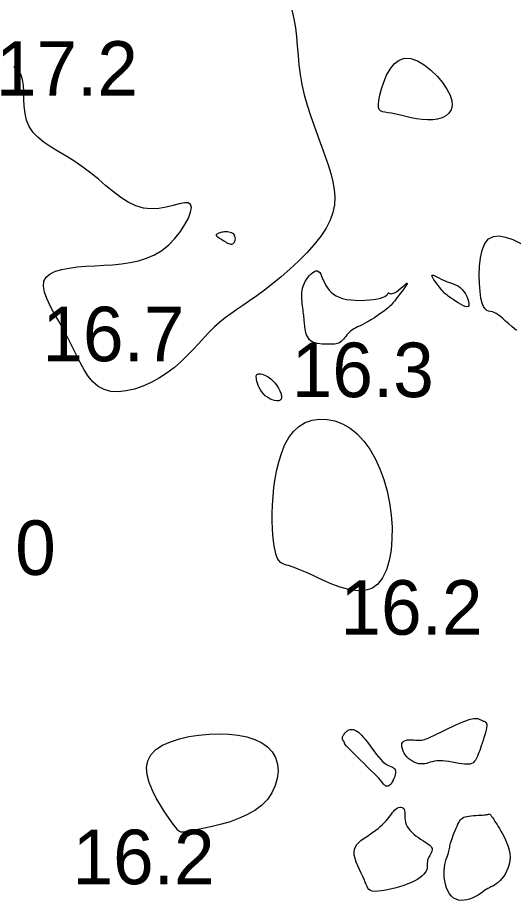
# Model space of a CAD drawing. Extents: x 3040093 to 3056816, y 408076 to 509144.
# Drawn here: x 3045881.2 to 3045926.6, y 434510.5 to 434591.4 of the extents above; entities that cross this region are included whole.
import ezdxf

# ---------------------------------------------------------------- set-up
doc = ezdxf.new("R2010")
doc.units = 0
doc.layers.add('V-CHAN-CONT-EL17', color=7, linetype='Continuous')
doc.layers.add('V-TOPO-SOUN-0610', color=7, linetype='Continuous')

msp = doc.modelspace()

# ---------------------------------------------------------------- linework, layer by layer
at = {"layer": 'V-CHAN-CONT-EL17'}
for points in [[(3045906.336, 434592.122), (3045906.528, 434591.309), (3045906.663, 434590.487), (3045906.758, 434589.655), (3045906.83, 434588.811), (3045906.898, 434587.952), (3045906.979, 434587.077), (3045907.09, 434586.183), (3045907.248, 434585.269), (3045907.465, 434584.335), (3045907.734, 434583.386), (3045908.04, 434582.433), (3045908.37, 434581.485), (3045908.71, 434580.55), (3045909.048, 434579.638), (3045909.368, 434578.757), (3045909.658, 434577.916), (3045909.905, 434577.122), (3045910.097, 434576.367), (3045910.223, 434575.642), (3045910.272, 434574.937), (3045910.233, 434574.242), (3045910.095, 434573.548), (3045909.848, 434572.845), (3045909.479, 434572.122), (3045908.985, 434571.374), (3045908.382, 434570.61), (3045907.695, 434569.844), (3045906.947, 434569.087), (3045906.161, 434568.353), (3045905.363, 434567.655), (3045904.574, 434567.005), (3045903.819, 434566.417), (3045903.117, 434565.9), (3045902.465, 434565.441), (3045901.858, 434565.026), (3045901.289, 434564.639), (3045900.751, 434564.264), (3045900.237, 434563.887), (3045899.741, 434563.492), (3045899.256, 434563.062), (3045898.776, 434562.588), (3045898.294, 434562.075), (3045897.801, 434561.536), (3045897.29, 434560.982), (3045896.753, 434560.424), (3045896.184, 434559.873), (3045895.575, 434559.34), (3045894.918, 434558.837), (3045894.21, 434558.376), (3045893.463, 434557.968), (3045892.695, 434557.626), (3045891.923, 434557.36), (3045891.164, 434557.183), (3045890.435, 434557.108), (3045889.752, 434557.146), (3045889.134, 434557.308), (3045888.591, 434557.603), (3045888.115, 434558.017), (3045887.69, 434558.534), (3045887.302, 434559.135), (3045886.937, 434559.805), (3045886.579, 434560.524), (3045886.214, 434561.277), (3045885.827, 434562.046), (3045885.411, 434562.814), (3045884.984, 434563.57), (3045884.572, 434564.302), (3045884.2, 434565.002), (3045883.894, 434565.657), (3045883.68, 434566.257), (3045883.584, 434566.792), (3045883.63, 434567.251), (3045883.838, 434567.626), (3045884.194, 434567.924), (3045884.677, 434568.155), (3045885.267, 434568.33), (3045885.943, 434568.458), (3045886.685, 434568.55), (3045887.472, 434568.616), (3045888.283, 434568.665), (3045889.1, 434568.708), (3045889.915, 434568.76), (3045890.722, 434568.836), (3045891.514, 434568.949), (3045892.287, 434569.114), (3045893.033, 434569.346), (3045893.748, 434569.66), (3045894.424, 434570.07), (3045895.055, 434570.583), (3045895.627, 434571.171), (3045896.128, 434571.798), (3045896.543, 434572.431), (3045896.857, 434573.032), (3045897.058, 434573.566), (3045897.131, 434573.998), (3045897.061, 434574.293), (3045896.842, 434574.427), (3045896.487, 434574.428), (3045896.02, 434574.338), (3045895.461, 434574.198), (3045894.832, 434574.048), (3045894.155, 434573.928), (3045893.45, 434573.881), (3045892.739, 434573.947), (3045892.04, 434574.156), (3045891.352, 434574.492), (3045890.67, 434574.929), (3045889.99, 434575.442), (3045889.307, 434576.003), (3045888.616, 434576.587), (3045887.913, 434577.167), (3045887.193, 434577.717), (3045886.455, 434578.218), (3045885.714, 434578.678), (3045884.989, 434579.112), (3045884.3, 434579.535), (3045883.664, 434579.962), (3045883.102, 434580.408), (3045882.631, 434580.888), (3045882.271, 434581.417), (3045882.033, 434582.004), (3045881.895, 434582.635), (3045881.827, 434583.291), (3045881.8, 434583.95), (3045881.783, 434584.593), (3045881.748, 434585.199), (3045881.664, 434585.749), (3045881.501, 434586.223), (3045881.238, 434586.606), (3045880.882, 434586.913)], [(3045926.911, 434562.741), (3045926.526, 434563.053), (3045926.194, 434563.339), (3045925.906, 434563.597), (3045925.656, 434563.824), (3045925.436, 434564.018), (3045925.238, 434564.178), (3045925.054, 434564.3), (3045924.876, 434564.384), (3045924.7, 434564.43), (3045924.525, 434564.459), (3045924.354, 434564.498), (3045924.19, 434564.57), (3045924.036, 434564.701), (3045923.894, 434564.916), (3045923.766, 434565.24), (3045923.656, 434565.698), (3045923.567, 434566.304), (3045923.508, 434567.023), (3045923.49, 434567.809), (3045923.521, 434568.616), (3045923.614, 434569.398), (3045923.777, 434570.108), (3045924.021, 434570.701), (3045924.356, 434571.13), (3045924.789, 434571.361), (3045925.312, 434571.408), (3045925.915, 434571.298), (3045926.587, 434571.056), (3045927.318, 434570.708)]]:
    msp.add_lwpolyline(points, dxfattribs=at)
for points in [[(3045917.229, 434587.653), (3045917.836, 434587.435), (3045918.455, 434587.071), (3045919.062, 434586.594), (3045919.629, 434586.042), (3045920.13, 434585.45), (3045920.54, 434584.853), (3045920.831, 434584.288), (3045920.985, 434583.783), (3045921.009, 434583.345), (3045920.918, 434582.972), (3045920.725, 434582.662), (3045920.447, 434582.415), (3045920.096, 434582.229), (3045919.688, 434582.104), (3045919.237, 434582.038), (3045918.757, 434582.028), (3045918.259, 434582.065), (3045917.753, 434582.138), (3045917.25, 434582.234), (3045916.761, 434582.344), (3045916.295, 434582.455), (3045915.862, 434582.557), (3045915.475, 434582.637), (3045915.14, 434582.69), (3045914.86, 434582.731), (3045914.634, 434582.778), (3045914.462, 434582.853), (3045914.343, 434582.975), (3045914.278, 434583.163), (3045914.266, 434583.437), (3045914.307, 434583.817), (3045914.401, 434584.313), (3045914.548, 434584.891), (3045914.752, 434585.509), (3045915.013, 434586.124), (3045915.332, 434586.692), (3045915.713, 434587.171), (3045916.155, 434587.517), (3045916.662, 434587.688)], [(3045901.004, 434570.725), (3045901.066, 434570.806), (3045901.113, 434570.905), (3045901.144, 434571.017), (3045901.158, 434571.135), (3045901.153, 434571.254), (3045901.127, 434571.368), (3045901.079, 434571.471), (3045901.007, 434571.557), (3045900.915, 434571.628), (3045900.806, 434571.684), (3045900.686, 434571.726), (3045900.558, 434571.754), (3045900.426, 434571.771), (3045900.294, 434571.776), (3045900.166, 434571.771), (3045900.046, 434571.757), (3045899.935, 434571.736), (3045899.834, 434571.709), (3045899.741, 434571.678), (3045899.659, 434571.644), (3045899.587, 434571.61), (3045899.527, 434571.576), (3045899.477, 434571.545), (3045899.439, 434571.517), (3045899.413, 434571.493), (3045899.397, 434571.47), (3045899.394, 434571.448), (3045899.401, 434571.426), (3045899.419, 434571.402), (3045899.448, 434571.376), (3045899.488, 434571.345), (3045899.538, 434571.31), (3045899.598, 434571.27), (3045899.666, 434571.226), (3045899.743, 434571.177), (3045899.828, 434571.125), (3045899.919, 434571.068), (3045900.015, 434571.007), (3045900.117, 434570.943), (3045900.224, 434570.877), (3045900.332, 434570.811), (3045900.441, 434570.75), (3045900.549, 434570.698), (3045900.654, 434570.66), (3045900.754, 434570.64), (3045900.847, 434570.642), (3045900.931, 434570.669)], [(3045907.403, 434564.262), (3045907.38, 434564.431), (3045907.355, 434564.61), (3045907.329, 434564.797), (3045907.305, 434564.991), (3045907.283, 434565.19), (3045907.265, 434565.391), (3045907.252, 434565.594), (3045907.245, 434565.797), (3045907.247, 434566), (3045907.259, 434566.202), (3045907.284, 434566.404), (3045907.323, 434566.605), (3045907.378, 434566.806), (3045907.453, 434567.007), (3045907.547, 434567.208), (3045907.663, 434567.407), (3045907.796, 434567.599), (3045907.942, 434567.776), (3045908.094, 434567.932), (3045908.249, 434568.059), (3045908.4, 434568.15), (3045908.543, 434568.198), (3045908.673, 434568.196), (3045908.786, 434568.139), (3045908.884, 434568.033), (3045908.974, 434567.887), (3045909.06, 434567.708), (3045909.146, 434567.506), (3045909.238, 434567.288), (3045909.34, 434567.063), (3045909.458, 434566.84), (3045909.594, 434566.625), (3045909.754, 434566.422), (3045909.939, 434566.234), (3045910.152, 434566.062), (3045910.395, 434565.909), (3045910.672, 434565.777), (3045910.985, 434565.668), (3045911.338, 434565.585), (3045911.729, 434565.529), (3045912.147, 434565.499), (3045912.58, 434565.491), (3045913.012, 434565.504), (3045913.431, 434565.534), (3045913.821, 434565.579), (3045914.169, 434565.636), (3045914.461, 434565.703), (3045914.688, 434565.777), (3045914.855, 434565.854), (3045914.972, 434565.93), (3045915.049, 434566.003), (3045915.096, 434566.067), (3045915.123, 434566.12), (3045915.141, 434566.158), (3045915.158, 434566.176), (3045915.184, 434566.174), (3045915.222, 434566.157), (3045915.274, 434566.134), (3045915.34, 434566.113), (3045915.424, 434566.101), (3045915.526, 434566.108), (3045915.649, 434566.141), (3045915.793, 434566.209), (3045915.96, 434566.315), (3045916.139, 434566.45), (3045916.322, 434566.6), (3045916.496, 434566.75), (3045916.653, 434566.886), (3045916.78, 434566.995), (3045916.868, 434567.061), (3045916.907, 434567.072), (3045916.888, 434567.017), (3045916.82, 434566.904), (3045916.712, 434566.746), (3045916.576, 434566.556), (3045916.422, 434566.346), (3045916.259, 434566.128), (3045916.1, 434565.915), (3045915.954, 434565.72), (3045915.829, 434565.552), (3045915.721, 434565.409), (3045915.622, 434565.283), (3045915.527, 434565.169), (3045915.427, 434565.061), (3045915.315, 434564.953), (3045915.185, 434564.838), (3045915.029, 434564.711), (3045914.843, 434564.567), (3045914.63, 434564.41), (3045914.397, 434564.244), (3045914.15, 434564.074), (3045913.896, 434563.904), (3045913.64, 434563.741), (3045913.389, 434563.588), (3045913.149, 434563.451), (3045912.925, 434563.332), (3045912.717, 434563.229), (3045912.525, 434563.138), (3045912.346, 434563.053), (3045912.18, 434562.971), (3045912.025, 434562.887), (3045911.881, 434562.796), (3045911.746, 434562.694), (3045911.619, 434562.578), (3045911.498, 434562.451), (3045911.383, 434562.318), (3045911.273, 434562.182), (3045911.165, 434562.05), (3045911.06, 434561.925), (3045910.955, 434561.812), (3045910.849, 434561.715), (3045910.742, 434561.638), (3045910.63, 434561.579), (3045910.513, 434561.537), (3045910.386, 434561.508), (3045910.249, 434561.489), (3045910.099, 434561.479), (3045909.934, 434561.474), (3045909.751, 434561.472), (3045909.55, 434561.471), (3045909.335, 434561.474), (3045909.113, 434561.484), (3045908.889, 434561.504), (3045908.67, 434561.538), (3045908.462, 434561.589), (3045908.27, 434561.66), (3045908.101, 434561.755), (3045907.96, 434561.875), (3045907.845, 434562.017), (3045907.752, 434562.175), (3045907.68, 434562.345), (3045907.624, 434562.521), (3045907.583, 434562.697), (3045907.552, 434562.869), (3045907.529, 434563.031), (3045907.511, 434563.18), (3045907.496, 434563.318), (3045907.485, 434563.448), (3045907.474, 434563.573), (3045907.464, 434563.698), (3045907.453, 434563.826), (3045907.44, 434563.96), (3045907.423, 434564.105)], [(3045919.941, 434566.593), (3045919.788, 434566.783), (3045919.631, 434566.985), (3045919.481, 434567.188), (3045919.348, 434567.379), (3045919.242, 434567.548), (3045919.176, 434567.682), (3045919.159, 434567.771), (3045919.2, 434567.805), (3045919.292, 434567.791), (3045919.428, 434567.738), (3045919.598, 434567.657), (3045919.793, 434567.557), (3045920.006, 434567.448), (3045920.226, 434567.339), (3045920.446, 434567.241), (3045920.658, 434567.16), (3045920.861, 434567.091), (3045921.055, 434567.026), (3045921.242, 434566.958), (3045921.422, 434566.879), (3045921.596, 434566.781), (3045921.763, 434566.657), (3045921.925, 434566.498), (3045922.08, 434566.3), (3045922.225, 434566.075), (3045922.351, 434565.835), (3045922.452, 434565.597), (3045922.522, 434565.373), (3045922.555, 434565.178), (3045922.543, 434565.026), (3045922.48, 434564.932), (3045922.362, 434564.906), (3045922.199, 434564.939), (3045922.002, 434565.018), (3045921.783, 434565.133), (3045921.554, 434565.27), (3045921.327, 434565.417), (3045921.113, 434565.561), (3045920.926, 434565.69), (3045920.772, 434565.795), (3045920.648, 434565.881), (3045920.545, 434565.955), (3045920.456, 434566.026), (3045920.373, 434566.1), (3045920.288, 434566.186), (3045920.192, 434566.293), (3045920.078, 434566.427)], [(3045903.481, 434558.749), (3045903.615, 434558.723), (3045903.764, 434558.678), (3045903.924, 434558.613), (3045904.094, 434558.524), (3045904.269, 434558.411), (3045904.448, 434558.269), (3045904.626, 434558.098), (3045904.8, 434557.897), (3045904.965, 434557.674), (3045905.112, 434557.439), (3045905.236, 434557.202), (3045905.33, 434556.974), (3045905.387, 434556.764), (3045905.4, 434556.583), (3045905.363, 434556.441), (3045905.271, 434556.345), (3045905.132, 434556.295), (3045904.957, 434556.287), (3045904.756, 434556.317), (3045904.539, 434556.382), (3045904.318, 434556.479), (3045904.103, 434556.603), (3045903.903, 434556.752), (3045903.728, 434556.921), (3045903.578, 434557.106), (3045903.451, 434557.301), (3045903.346, 434557.5), (3045903.26, 434557.697), (3045903.192, 434557.887), (3045903.141, 434558.065), (3045903.104, 434558.225), (3045903.081, 434558.362), (3045903.072, 434558.476), (3045903.078, 434558.569), (3045903.099, 434558.643), (3045903.138, 434558.697), (3045903.194, 434558.733), (3045903.27, 434558.754), (3045903.365, 434558.758)], [(3045904.81, 434549.147), (3045904.961, 434549.971), (3045905.157, 434550.777), (3045905.402, 434551.548), (3045905.702, 434552.268), (3045906.062, 434552.918), (3045906.488, 434553.481), (3045906.984, 434553.942), (3045907.554, 434554.284), (3045908.183, 434554.505), (3045908.857, 434554.604), (3045909.559, 434554.581), (3045910.273, 434554.434), (3045910.983, 434554.163), (3045911.672, 434553.766), (3045912.325, 434553.244), (3045912.928, 434552.599), (3045913.476, 434551.842), (3045913.965, 434550.989), (3045914.393, 434550.056), (3045914.757, 434549.057), (3045915.053, 434548.008), (3045915.279, 434546.924), (3045915.431, 434545.821), (3045915.508, 434544.715), (3045915.505, 434543.632), (3045915.419, 434542.597), (3045915.249, 434541.637), (3045914.99, 434540.779), (3045914.64, 434540.049), (3045914.197, 434539.473), (3045913.656, 434539.078), (3045913.02, 434538.881), (3045912.309, 434538.857), (3045911.549, 434538.973), (3045910.765, 434539.193), (3045909.982, 434539.483), (3045909.226, 434539.811), (3045908.521, 434540.14), (3045907.893, 434540.438), (3045907.362, 434540.677), (3045906.921, 434540.86), (3045906.56, 434540.997), (3045906.265, 434541.098), (3045906.027, 434541.172), (3045905.832, 434541.23), (3045905.67, 434541.282), (3045905.528, 434541.338), (3045905.398, 434541.406), (3045905.276, 434541.497), (3045905.163, 434541.618), (3045905.058, 434541.777), (3045904.962, 434541.984), (3045904.874, 434542.245), (3045904.794, 434542.569), (3045904.722, 434542.965), (3045904.659, 434543.439), (3045904.606, 434543.984), (3045904.567, 434544.593), (3045904.546, 434545.259), (3045904.545, 434545.972), (3045904.567, 434546.726), (3045904.617, 434547.512), (3045904.697, 434548.322)], [(3045917.972, 434525.163), (3045918.102, 434525.161), (3045918.224, 434525.17), (3045918.349, 434525.193), (3045918.485, 434525.231), (3045918.643, 434525.289), (3045918.83, 434525.368), (3045919.057, 434525.472), (3045919.33, 434525.602), (3045919.641, 434525.753), (3045919.98, 434525.918), (3045920.336, 434526.092), (3045920.699, 434526.267), (3045921.058, 434526.437), (3045921.402, 434526.596), (3045921.721, 434526.738), (3045922.006, 434526.857), (3045922.258, 434526.953), (3045922.48, 434527.029), (3045922.674, 434527.086), (3045922.844, 434527.126), (3045922.992, 434527.15), (3045923.12, 434527.161), (3045923.232, 434527.16), (3045923.33, 434527.149), (3045923.417, 434527.13), (3045923.495, 434527.105), (3045923.565, 434527.075), (3045923.631, 434527.043), (3045923.694, 434527.01), (3045923.756, 434526.979), (3045923.821, 434526.952), (3045923.888, 434526.929), (3045923.955, 434526.906), (3045924.02, 434526.878), (3045924.079, 434526.839), (3045924.128, 434526.785), (3045924.165, 434526.709), (3045924.186, 434526.608), (3045924.187, 434526.475), (3045924.167, 434526.307), (3045924.127, 434526.109), (3045924.072, 434525.888), (3045924.005, 434525.65), (3045923.929, 434525.402), (3045923.849, 434525.151), (3045923.766, 434524.903), (3045923.686, 434524.666), (3045923.61, 434524.444), (3045923.538, 434524.239), (3045923.47, 434524.05), (3045923.404, 434523.877), (3045923.34, 434523.72), (3045923.275, 434523.577), (3045923.21, 434523.449), (3045923.142, 434523.336), (3045923.071, 434523.236), (3045922.993, 434523.151), (3045922.903, 434523.08), (3045922.798, 434523.026), (3045922.673, 434522.987), (3045922.524, 434522.965), (3045922.346, 434522.961), (3045922.137, 434522.974), (3045921.893, 434523.005), (3045921.62, 434523.049), (3045921.328, 434523.101), (3045921.024, 434523.155), (3045920.716, 434523.207), (3045920.412, 434523.249), (3045920.121, 434523.278), (3045919.851, 434523.288), (3045919.608, 434523.275), (3045919.39, 434523.244), (3045919.191, 434523.199), (3045919.007, 434523.148), (3045918.834, 434523.096), (3045918.665, 434523.049), (3045918.498, 434523.013), (3045918.326, 434522.993), (3045918.147, 434522.995), (3045917.962, 434523.019), (3045917.774, 434523.066), (3045917.587, 434523.134), (3045917.402, 434523.224), (3045917.224, 434523.336), (3045917.055, 434523.468), (3045916.898, 434523.622), (3045916.756, 434523.795), (3045916.632, 434523.981), (3045916.531, 434524.175), (3045916.456, 434524.368), (3045916.41, 434524.555), (3045916.397, 434524.727), (3045916.421, 434524.879), (3045916.485, 434525.002), (3045916.591, 434525.093), (3045916.732, 434525.154), (3045916.899, 434525.19), (3045917.084, 434525.207), (3045917.278, 434525.208), (3045917.472, 434525.199), (3045917.658, 434525.186), (3045917.826, 434525.172)], [(3045893.431, 434523.835), (3045893.891, 434524.307), (3045894.495, 434524.706), (3045895.216, 434525.035), (3045896.029, 434525.299), (3045896.907, 434525.499), (3045897.824, 434525.638), (3045898.754, 434525.721), (3045899.674, 434525.747), (3045900.566, 434525.716), (3045901.416, 434525.624), (3045902.211, 434525.466), (3045902.934, 434525.239), (3045903.573, 434524.939), (3045904.113, 434524.564), (3045904.539, 434524.109), (3045904.839, 434523.574), (3045905.014, 434522.976), (3045905.066, 434522.335), (3045904.997, 434521.672), (3045904.81, 434521.007), (3045904.507, 434520.359), (3045904.091, 434519.75), (3045903.564, 434519.199), (3045902.934, 434518.723), (3045902.223, 434518.318), (3045901.462, 434517.979), (3045900.678, 434517.698), (3045899.899, 434517.468), (3045899.155, 434517.283), (3045898.474, 434517.135), (3045897.884, 434517.018), (3045897.407, 434516.926), (3045897.035, 434516.855), (3045896.753, 434516.803), (3045896.546, 434516.767), (3045896.398, 434516.746), (3045896.296, 434516.737), (3045896.224, 434516.737), (3045896.167, 434516.745), (3045896.111, 434516.76), (3045896.048, 434516.793), (3045895.967, 434516.856), (3045895.862, 434516.964), (3045895.724, 434517.128), (3045895.544, 434517.362), (3045895.314, 434517.678), (3045895.027, 434518.091), (3045894.679, 434518.606), (3045894.298, 434519.206), (3045893.917, 434519.868), (3045893.567, 434520.568), (3045893.281, 434521.284), (3045893.093, 434521.992), (3045893.035, 434522.668), (3045893.14, 434523.288)], [(3045911.026, 434525.153), (3045911.008, 434525.178), (3045910.992, 434525.206), (3045910.978, 434525.237), (3045910.967, 434525.272), (3045910.962, 434525.312), (3045910.962, 434525.358), (3045910.97, 434525.41), (3045910.987, 434525.468), (3045911.011, 434525.531), (3045911.044, 434525.598), (3045911.083, 434525.668), (3045911.128, 434525.738), (3045911.179, 434525.807), (3045911.236, 434525.874), (3045911.297, 434525.937), (3045911.362, 434525.994), (3045911.431, 434526.044), (3045911.505, 434526.087), (3045911.584, 434526.121), (3045911.668, 434526.144), (3045911.757, 434526.155), (3045911.852, 434526.154), (3045911.953, 434526.139), (3045912.061, 434526.108), (3045912.175, 434526.059), (3045912.298, 434525.991), (3045912.428, 434525.899), (3045912.568, 434525.782), (3045912.719, 434525.637), (3045912.88, 434525.462), (3045913.052, 434525.254), (3045913.237, 434525.013), (3045913.431, 434524.747), (3045913.633, 434524.466), (3045913.841, 434524.181), (3045914.051, 434523.902), (3045914.262, 434523.638), (3045914.472, 434523.401), (3045914.677, 434523.201), (3045914.876, 434523.044), (3045915.065, 434522.925), (3045915.241, 434522.833), (3045915.4, 434522.76), (3045915.54, 434522.694), (3045915.655, 434522.627), (3045915.744, 434522.549), (3045915.803, 434522.45), (3045915.83, 434522.324), (3045915.827, 434522.174), (3045915.799, 434522.009), (3045915.752, 434521.836), (3045915.688, 434521.663), (3045915.614, 434521.496), (3045915.533, 434521.344), (3045915.45, 434521.214), (3045915.368, 434521.112), (3045915.29, 434521.036), (3045915.214, 434520.985), (3045915.143, 434520.955), (3045915.075, 434520.944), (3045915.011, 434520.949), (3045914.953, 434520.967), (3045914.9, 434520.997), (3045914.851, 434521.036), (3045914.801, 434521.087), (3045914.742, 434521.155), (3045914.669, 434521.244), (3045914.573, 434521.358), (3045914.449, 434521.502), (3045914.288, 434521.679), (3045914.085, 434521.893), (3045913.835, 434522.148), (3045913.549, 434522.433), (3045913.238, 434522.738), (3045912.915, 434523.053), (3045912.594, 434523.365), (3045912.287, 434523.665), (3045912.007, 434523.942), (3045911.766, 434524.184), (3045911.574, 434524.383), (3045911.428, 434524.542), (3045911.321, 434524.666), (3045911.246, 434524.76), (3045911.197, 434524.831), (3045911.168, 434524.882), (3045911.152, 434524.921), (3045911.141, 434524.951), (3045911.132, 434524.977), (3045911.122, 434525.002), (3045911.111, 434525.024), (3045911.1, 434525.046), (3045911.087, 434525.066), (3045911.074, 434525.087), (3045911.059, 434525.108), (3045911.043, 434525.13)], [(3045912.066, 434515.172), (3045912.155, 434515.402), (3045912.29, 434515.609), (3045912.461, 434515.797), (3045912.66, 434515.97), (3045912.88, 434516.133), (3045913.111, 434516.29), (3045913.346, 434516.445), (3045913.577, 434516.603), (3045913.803, 434516.763), (3045914.021, 434516.924), (3045914.23, 434517.088), (3045914.428, 434517.253), (3045914.615, 434517.418), (3045914.789, 434517.585), (3045914.948, 434517.752), (3045915.092, 434517.919), (3045915.223, 434518.083), (3045915.343, 434518.242), (3045915.455, 434518.394), (3045915.562, 434518.534), (3045915.666, 434518.662), (3045915.771, 434518.774), (3045915.878, 434518.867), (3045915.991, 434518.94), (3045916.105, 434518.991), (3045916.218, 434519.02), (3045916.325, 434519.025), (3045916.424, 434519.008), (3045916.51, 434518.966), (3045916.58, 434518.899), (3045916.63, 434518.806), (3045916.659, 434518.689), (3045916.671, 434518.549), (3045916.674, 434518.39), (3045916.676, 434518.216), (3045916.683, 434518.031), (3045916.702, 434517.839), (3045916.741, 434517.643), (3045916.807, 434517.447), (3045916.905, 434517.254), (3045917.032, 434517.066), (3045917.183, 434516.883), (3045917.354, 434516.708), (3045917.539, 434516.541), (3045917.734, 434516.383), (3045917.933, 434516.236), (3045918.131, 434516.1), (3045918.325, 434515.976), (3045918.508, 434515.862), (3045918.678, 434515.755), (3045918.831, 434515.653), (3045918.961, 434515.553), (3045919.065, 434515.452), (3045919.138, 434515.347), (3045919.177, 434515.236), (3045919.18, 434515.117), (3045919.151, 434514.991), (3045919.1, 434514.859), (3045919.033, 434514.724), (3045918.959, 434514.586), (3045918.885, 434514.449), (3045918.82, 434514.313), (3045918.77, 434514.181), (3045918.742, 434514.053), (3045918.731, 434513.929), (3045918.73, 434513.807), (3045918.732, 434513.685), (3045918.73, 434513.563), (3045918.717, 434513.439), (3045918.686, 434513.31), (3045918.631, 434513.177), (3045918.545, 434513.037), (3045918.427, 434512.891), (3045918.274, 434512.742), (3045918.087, 434512.591), (3045917.863, 434512.439), (3045917.602, 434512.288), (3045917.302, 434512.139), (3045916.963, 434511.994), (3045916.586, 434511.855), (3045916.181, 434511.724), (3045915.762, 434511.606), (3045915.343, 434511.503), (3045914.936, 434511.418), (3045914.556, 434511.356), (3045914.215, 434511.319), (3045913.927, 434511.31), (3045913.701, 434511.333), (3045913.529, 434511.388), (3045913.399, 434511.476), (3045913.299, 434511.596), (3045913.217, 434511.748), (3045913.14, 434511.934), (3045913.057, 434512.152), (3045912.955, 434512.403), (3045912.826, 434512.686), (3045912.678, 434512.994), (3045912.522, 434513.319), (3045912.37, 434513.653), (3045912.233, 434513.988), (3045912.123, 434514.315), (3045912.051, 434514.626), (3045912.03, 434514.914)], [(3045920.955, 434510.876), (3045920.782, 434511.098), (3045920.633, 434511.359), (3045920.509, 434511.65), (3045920.41, 434511.962), (3045920.338, 434512.285), (3045920.292, 434512.61), (3045920.272, 434512.927), (3045920.28, 434513.23), (3045920.309, 434513.516), (3045920.356, 434513.784), (3045920.415, 434514.033), (3045920.48, 434514.264), (3045920.548, 434514.474), (3045920.612, 434514.665), (3045920.667, 434514.834), (3045920.711, 434514.983), (3045920.744, 434515.116), (3045920.771, 434515.238), (3045920.794, 434515.356), (3045920.817, 434515.475), (3045920.843, 434515.6), (3045920.876, 434515.738), (3045920.919, 434515.893), (3045920.975, 434516.07), (3045921.042, 434516.265), (3045921.117, 434516.472), (3045921.199, 434516.684), (3045921.285, 434516.896), (3045921.372, 434517.102), (3045921.459, 434517.296), (3045921.543, 434517.472), (3045921.622, 434517.625), (3045921.701, 434517.756), (3045921.782, 434517.868), (3045921.87, 434517.961), (3045921.969, 434518.038), (3045922.084, 434518.1), (3045922.218, 434518.15), (3045922.375, 434518.19), (3045922.557, 434518.22), (3045922.76, 434518.244), (3045922.975, 434518.261), (3045923.195, 434518.275), (3045923.412, 434518.285), (3045923.618, 434518.295), (3045923.806, 434518.304), (3045923.969, 434518.316), (3045924.1, 434518.33), (3045924.202, 434518.346), (3045924.28, 434518.363), (3045924.337, 434518.378), (3045924.379, 434518.391), (3045924.408, 434518.4), (3045924.431, 434518.403), (3045924.451, 434518.399), (3045924.471, 434518.387), (3045924.494, 434518.366), (3045924.52, 434518.336), (3045924.55, 434518.297), (3045924.584, 434518.248), (3045924.625, 434518.189), (3045924.672, 434518.12), (3045924.726, 434518.04), (3045924.788, 434517.949), (3045924.859, 434517.845), (3045924.938, 434517.726), (3045925.027, 434517.591), (3045925.126, 434517.437), (3045925.234, 434517.262), (3045925.353, 434517.064), (3045925.482, 434516.842), (3045925.621, 434516.594), (3045925.765, 434516.323), (3045925.905, 434516.034), (3045926.036, 434515.73), (3045926.15, 434515.414), (3045926.24, 434515.092), (3045926.3, 434514.767), (3045926.323, 434514.442), (3045926.303, 434514.122), (3045926.245, 434513.81), (3045926.154, 434513.509), (3045926.035, 434513.223), (3045925.895, 434512.956), (3045925.738, 434512.71), (3045925.571, 434512.49), (3045925.4, 434512.298), (3045925.228, 434512.137), (3045925.058, 434512.002), (3045924.891, 434511.891), (3045924.729, 434511.796), (3045924.572, 434511.715), (3045924.421, 434511.641), (3045924.279, 434511.57), (3045924.145, 434511.498), (3045924.02, 434511.419), (3045923.901, 434511.336), (3045923.782, 434511.248), (3045923.66, 434511.157), (3045923.529, 434511.063), (3045923.385, 434510.968), (3045923.224, 434510.874), (3045923.041, 434510.781), (3045922.833, 434510.69), (3045922.604, 434510.609), (3045922.361, 434510.544), (3045922.11, 434510.502), (3045921.857, 434510.49), (3045921.609, 434510.515), (3045921.372, 434510.583), (3045921.152, 434510.702)]]:
    msp.add_lwpolyline(points, close=True, dxfattribs=at)

# ---------------------------------------------------------------- texts
at = {"layer": 'V-TOPO-SOUN-0610'}
for s, p in [('17.2 ', (3045879.223, 434584.25)), ('16.7 ', (3045883.483, 434559.91)), ('16.3 ', (3045906.323, 434556.62)), ('16.0 ', (3045871.703, 434540.32)), ('16.2 ', (3045910.783, 434534.84)), ('16.2 ', (3045886.243, 434511.97))]:
    msp.add_text(s, height=5, dxfattribs=at).set_placement(p)

doc.saveas('drawing.dxf')
